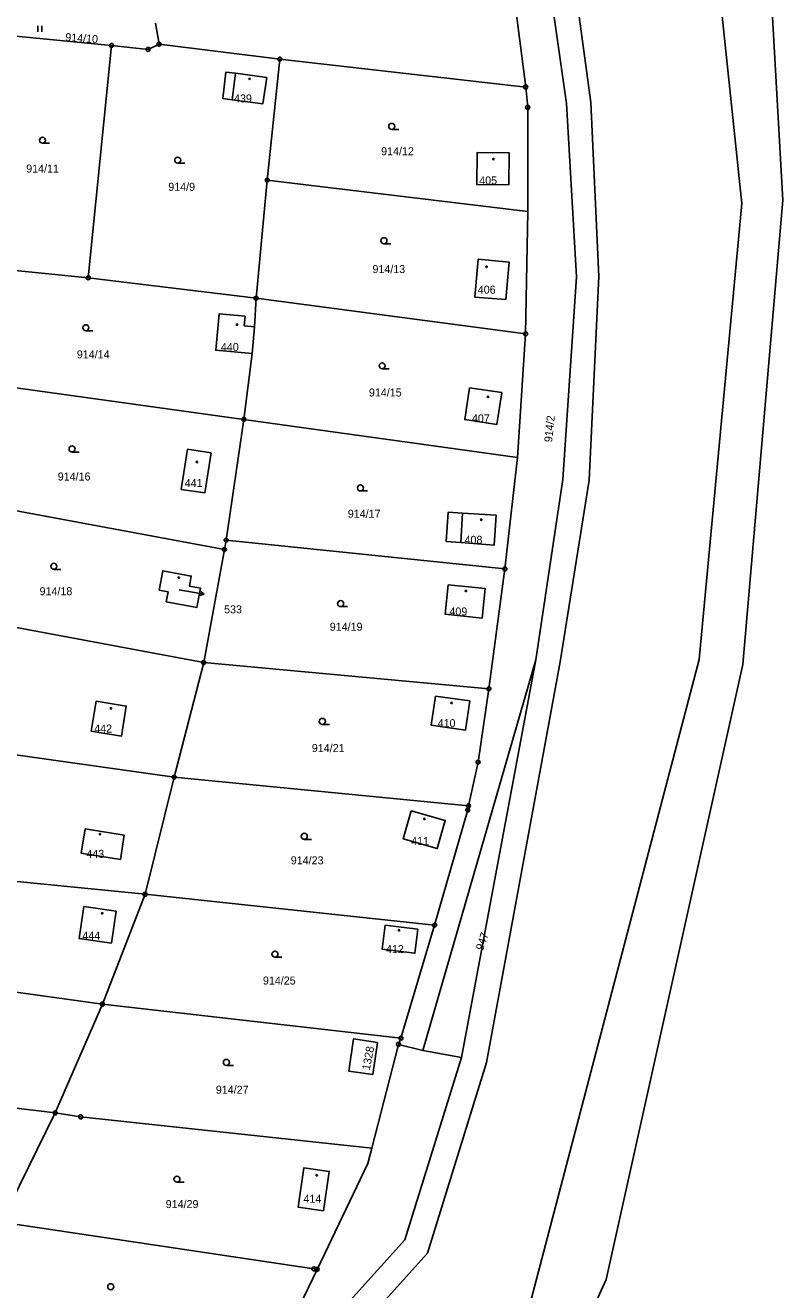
# Model space of a CAD drawing. Extents: x -745926 to -742978, y -968282 to -965689.
# Drawn here: x -744074.2 to -743979.6, y -968038.9 to -967880.9 of the extents above; entities that cross this region are included whole.
import ezdxf

# ---------------------------------------------------------------- set-up
doc = ezdxf.new("R2010")
doc.units = 0
for name, color, linetype in [('Hranice parcel', 7, 'Continuous'), ('Parcelní čísla', 7, 'Continuous'), ('Pop  PČ popisy', 7, 'Continuous'), ('Vnitřní kresba', 7, 'Continuous'), ('Značky bodu BP', 7, 'Continuous'), ('Značky budov', 7, 'Continuous'), ('Značky kultur', 7, 'Continuous')]:
    doc.layers.add(name, color=color, linetype=linetype)

msp = doc.modelspace()

# ---------------------------------------------------------------- linework, layer by layer
at = {"layer": 'Hranice parcel'}
for p, q in [((-744013.88, -967871.59), (-744011.71, -967888.67)), ((-744057.93, -967880.69), (-744057.5, -967883.31)), ((-744076.69, -967882.2), (-744063.43, -967883.47)), ((-744063.43, -967883.47), (-744066.34, -967912.5)), ((-744057.5, -967883.31), (-744042.42, -967885.18)), ((-744043.99, -967900.3), (-744042.42, -967885.18)), ((-744042.42, -967885.18), (-744011.71, -967888.67)), ((-744045.39, -967915.05), (-744043.99, -967900.3)), ((-744043.99, -967900.3), (-744011.44, -967904.22)), ((-744011.44, -967904.22), (-744011.72, -967919.51)), ((-744066.34, -967912.5), (-744045.39, -967915.05)), ((-744045.57, -967918.61), (-744045.39, -967915.05)), ((-744045.39, -967915.05), (-744011.72, -967919.51)), ((-744045.89, -967921.98), (-744045.57, -967918.61)), ((-744011.72, -967919.51), (-744012.73, -967934.97)), ((-744046.92, -967930.19), (-744045.89, -967921.98)), ((-744081.74, -967925.39), (-744046.92, -967930.19)), ((-744049.12, -967945.28), (-744046.92, -967930.19)), ((-744046.92, -967930.19), (-744012.73, -967934.97)), ((-744012.73, -967934.97), (-744014.31, -967948.88)), ((-744084.27, -967939.93), (-744049.34, -967946.46)), ((-744049.34, -967946.46), (-744049.12, -967945.28)), ((-744049.12, -967945.28), (-744014.31, -967948.88)), ((-744051.92, -967960.57), (-744049.34, -967946.46)), ((-744014.31, -967948.88), (-744016.31, -967963.85)), ((-744086.86, -967954.05), (-744051.92, -967960.57)), ((-744010.44, -967960.22), (-744024.55, -968009.03)), ((-744019.73, -968009.91), (-744010.44, -967960.22)), ((-744055.61, -967974.9), (-744051.92, -967960.57)), ((-744051.92, -967960.57), (-744016.31, -967963.85)), ((-744093.25, -967969.59), (-744055.61, -967974.9)), ((-744059.25, -967989.53), (-744055.61, -967974.9)), ((-744055.61, -967974.9), (-744018.86, -967978.48)), ((-744100.21, -967985.49), (-744059.25, -967989.53)), ((-744064.58, -968003.26), (-744059.25, -967989.53)), ((-744059.25, -967989.53), (-744023.1, -967993.38)), ((-744023.1, -967993.38), (-744027.29, -968007.5)), ((-744105.52, -967997.54), (-744064.58, -968003.26)), ((-744070.47, -968016.85), (-744064.58, -968003.26)), ((-744064.58, -968003.26), (-744027.29, -968007.5)), ((-744027.29, -968007.5), (-744027.6, -968008.29)), ((-744027.6, -968008.29), (-744030.93, -968021.24)), ((-744024.55, -968009.03), (-744027.6, -968008.29)), ((-744019.73, -968009.91), (-744024.55, -968009.03)), ((-744111.82, -968011.94), (-744070.47, -968016.85)), ((-744077.16, -968030.5), (-744070.47, -968016.85))]:
    msp.add_line(p, q, dxfattribs=at)
for points in [[(-744010.44, -967960.22), (-744007.08, -967937.69), (-744005.36, -967912.38), (-744006.62, -967890.72), (-744010, -967867.02), (-744009.12, -967862.36)], [(-744014.05, -968065.04), (-744001.65, -968037.67), (-743984.6, -967960.81), (-743979.62, -967902.8), (-743981.26, -967873.23)], [(-744057.5, -967883.31), (-744058.87, -967883.96), (-744063.43, -967883.47)], [(-744044.03, -967887.46), (-744047.94, -967886.95), (-744049.14, -967886.8), (-744049.54, -967890.09), (-744048.35, -967890.25), (-744044.52, -967890.76), (-744044.03, -967887.46)], [(-744011.71, -967888.67), (-744011.46, -967891.2), (-744011.44, -967904.22)], [(-744013.81, -967900.88), (-744013.79, -967896.88), (-744017.79, -967896.86), (-744017.81, -967900.86), (-744013.81, -967900.88)], [(-744079.82, -967911.15), (-744078.78, -967911.25), (-744066.34, -967912.5)], [(-744018.08, -967914.92), (-744014.18, -967915.21), (-744013.78, -967910.53), (-744017.66, -967910.19), (-744018.08, -967914.92)], [(-744045.57, -967918.61), (-744046.86, -967918.49), (-744046.75, -967917.3), (-744049.99, -967916.99), (-744050.42, -967921.56), (-744045.89, -967921.98)], [(-744018.73, -967926.23), (-744019.33, -967930.22), (-744015.31, -967930.83), (-744014.7, -967926.84), (-744018.73, -967926.23)], [(-744051.01, -967934.37), (-744053.93, -967933.92), (-744054.72, -967938.94), (-744051.8, -967939.39), (-744051.01, -967934.37)], [(-744019.59, -967941.89), (-744021.39, -967941.77), (-744021.64, -967945.47), (-744019.8, -967945.59), (-744015.64, -967945.9), (-744015.39, -967942.17), (-744019.59, -967941.89)], [(-744057.49, -967951.55), (-744056.37, -967951.76), (-744056.6, -967952.98), (-744052.79, -967953.7), (-744052.34, -967951.28), (-744053.71, -967951.02), (-744053.48, -967949.78), (-744057.03, -967949.11), (-744057.49, -967951.55)], [(-744021.38, -967950.85), (-744021.77, -967954.53), (-744017.16, -967955.03), (-744016.77, -967951.34), (-744021.38, -967950.85)], [(-744022.98, -967964.77), (-744023.5, -967968.42), (-744019.24, -967969.03), (-744018.7, -967965.38), (-744022.98, -967964.77)], [(-744016.31, -967963.85), (-744017.66, -967973.03), (-744018.86, -967978.48)], [(-744065.36, -967965.4), (-744065.97, -967969.17), (-744062.2, -967969.78), (-744061.59, -967966.01), (-744065.36, -967965.4)], [(-744026, -967979.12), (-744027.01, -967982.59), (-744022.79, -967983.82), (-744021.76, -967980.3), (-744026, -967979.12)], [(-744018.86, -967978.48), (-744018.95, -967978.99), (-744023.1, -967993.38)], [(-744066.74, -967981.37), (-744067.22, -967984.4), (-744062.32, -967985.18), (-744061.84, -967982.15), (-744066.74, -967981.37)], [(-744063.45, -967995.65), (-744062.87, -967991.65), (-744066.89, -967991.06), (-744067.48, -967995.06), (-744063.45, -967995.65)], [(-744025.18, -967993.91), (-744029.25, -967993.41), (-744029.62, -967996.39), (-744025.55, -967996.9), (-744025.18, -967993.91)], [(-744030.22, -968008.06), (-744030.81, -968012.07), (-744033.82, -968011.63), (-744033.22, -968007.61), (-744030.22, -968008.06)], [(-744238.47, -968250.81), (-744228.48, -968220.23), (-744215.49, -968202.15), (-744184.43, -968175.45), (-744137.25, -968142.28), (-744118.9, -968127.71), (-744107.2, -968119.2), (-744080.31, -968095.84), (-744060.74, -968076.33), (-744040.78, -968053.44), (-744033.64, -968040.28), (-744026.79, -968032.71), (-744019.73, -968009.91)], [(-744070.47, -968016.85), (-744067.29, -968017.34), (-744030.93, -968021.24)], [(-744030.93, -968021.24), (-744031.42, -968023.15), (-744037.77, -968036.4)], [(-744036.95, -968029.09), (-744036.25, -968024.15), (-744039.41, -968023.7), (-744040.11, -968028.64), (-744036.95, -968029.09)], [(-744077.16, -968030.5), (-744038.16, -968036.34), (-744037.77, -968036.4)], [(-744037.77, -968036.4), (-744040.52, -968042.14), (-744046.13, -968050.07)]]:
    msp.add_lwpolyline(points, dxfattribs=at)
at = {"layer": 'Pop  PČ popisy'}
for p, q in [((-744054.99, -967951.49), (-744053.33, -967951.78)), ((-744053.33, -967951.78), (-744051.85, -967952.04)), ((-744051.85, -967952.04), (-744052.39, -967952.2)), ((-744051.85, -967952.04), (-744052.3, -967951.71))]:
    msp.add_line(p, q, dxfattribs=at)
at = {"layer": 'Vnitřní kresba'}
for p, q in [((-744003.59, -967890.59), (-744006.8, -967866.88)), ((-743987.62, -967875.34), (-743984.73, -967903.21)), ((-744047.94, -967886.95), (-744048.35, -967890.25)), ((-744002.57, -967912.33), (-744003.59, -967890.59)), ((-743984.73, -967903.21), (-743990.05, -967960.19)), ((-744003.8, -967937.79), (-744002.57, -967912.33)), ((-744007.4, -967960.49), (-744003.8, -967937.79)), ((-744019.59, -967941.89), (-744019.8, -967945.59)), ((-743990.05, -967960.19), (-744017.1, -968063.19)), ((-744016.6, -968010.57), (-744007.4, -967960.49)), ((-744023.98, -968034.39), (-744016.6, -968010.57)), ((-744030.76, -968041.91), (-744023.98, -968034.39))]:
    msp.add_line(p, q, dxfattribs=at)
at = {"layer": 'Značky bodu BP'}
for centre, radius in [((-744063.43, -967883.47), 0.25), ((-744063.43, -967883.47), 0.0152), ((-744058.87, -967883.96), 0.25), ((-744058.87, -967883.96), 0.0152), ((-744057.5, -967883.31), 0.25), ((-744057.5, -967883.31), 0.0152), ((-744042.42, -967885.18), 0.25), ((-744042.42, -967885.18), 0.0152), ((-744011.71, -967888.67), 0.25), ((-744011.71, -967888.67), 0.0152), ((-744011.46, -967891.2), 0.25), ((-744011.46, -967891.2), 0.0152), ((-744043.99, -967900.3), 0.25), ((-744043.99, -967900.3), 0.0152), ((-744066.34, -967912.5), 0.25), ((-744066.34, -967912.5), 0.0152), ((-744045.39, -967915.05), 0.25), ((-744045.39, -967915.05), 0.0152), ((-744011.72, -967919.51), 0.25), ((-744011.72, -967919.51), 0.0152), ((-744046.92, -967930.19), 0.25), ((-744046.92, -967930.19), 0.0152), ((-744049.12, -967945.28), 0.25), ((-744049.12, -967945.28), 0.0152), ((-744049.34, -967946.46), 0.25), ((-744049.34, -967946.46), 0.0152), ((-744014.31, -967948.88), 0.25), ((-744014.31, -967948.88), 0.0152), ((-744051.92, -967960.57), 0.25), ((-744051.92, -967960.57), 0.0152), ((-744016.31, -967963.85), 0.25), ((-744016.31, -967963.85), 0.0152), ((-744017.66, -967973.03), 0.25), ((-744017.66, -967973.03), 0.0152), ((-744055.61, -967974.9), 0.25), ((-744055.61, -967974.9), 0.0152), ((-744018.95, -967978.99), 0.25), ((-744018.86, -967978.48), 0.25), ((-744018.95, -967978.99), 0.0152), ((-744018.86, -967978.48), 0.0152), ((-744059.25, -967989.53), 0.25), ((-744059.25, -967989.53), 0.0152), ((-744023.1, -967993.38), 0.25), ((-744023.1, -967993.38), 0.0152), ((-744064.58, -968003.26), 0.25), ((-744064.58, -968003.26), 0.0152), ((-744027.29, -968007.5), 0.25), ((-744027.29, -968007.5), 0.0152), ((-744027.6, -968008.29), 0.25), ((-744027.6, -968008.29), 0.0152), ((-744070.47, -968016.85), 0.25), ((-744070.47, -968016.85), 0.0152), ((-744067.29, -968017.34), 0.25), ((-744067.29, -968017.34), 0.0152), ((-744038.16, -968036.34), 0.25), ((-744037.77, -968036.4), 0.25), ((-744038.16, -968036.34), 0.0152), ((-744037.77, -968036.4), 0.0152)]:
    msp.add_circle(centre, radius, dxfattribs=at)
at = {"layer": 'Značky budov'}
for centre in [(-744046.19, -967887.64), (-744015.75, -967897.67), (-744016.6, -967911.13), (-744047.77, -967918.36), (-744016.42, -967927.39), (-744052.77, -967935.52), (-744017.27, -967942.73), (-744055.04, -967949.95), (-744019.18, -967951.63), (-744063.52, -967966.31), (-744020.97, -967965.61), (-744024.36, -967980.11), (-744064.88, -967982.02), (-744064.59, -967991.9), (-744027.52, -967994.02), (-744037.81, -968024.63)]:
    msp.add_circle(centre, 0.0875, dxfattribs=at)
at = {"layer": 'Značky kultur'}
for p, q in [((-744072.63, -967881.75), (-744072.63, -967881)), ((-744072.12, -967881.75), (-744072.12, -967881)), ((-744028.45, -967893.96), (-744027.57, -967893.96)), ((-744072.05, -967895.69), (-744071.17, -967895.69)), ((-744055.17, -967898.18), (-744054.29, -967898.18)), ((-744029.42, -967908.25), (-744028.54, -967908.25)), ((-744066.64, -967919.12), (-744065.76, -967919.12)), ((-744029.64, -967923.88), (-744028.76, -967923.88)), ((-744068.37, -967934.27), (-744067.49, -967934.27)), ((-744032.35, -967939.14), (-744031.47, -967939.14)), ((-744070.64, -967948.93), (-744069.76, -967948.93)), ((-744034.83, -967953.59), (-744033.95, -967953.59)), ((-744037.11, -967968.31), (-744036.23, -967968.31)), ((-744039.36, -967982.67), (-744038.48, -967982.67)), ((-744043.03, -967997.39), (-744042.15, -967997.39)), ((-744049.09, -968010.92), (-744048.21, -968010.92)), ((-744055.26, -968025.51), (-744054.38, -968025.51))]:
    msp.add_line(p, q, dxfattribs=at)
for centre in [(-744028.45, -967893.58), (-744072.05, -967895.31), (-744055.17, -967897.8), (-744029.42, -967907.87), (-744066.64, -967918.74), (-744029.64, -967923.5), (-744068.37, -967933.89), (-744032.35, -967938.76), (-744070.64, -967948.55), (-744034.83, -967953.21), (-744037.11, -967967.93), (-744039.36, -967982.29), (-744043.03, -967997.01), (-744049.09, -968010.54), (-744055.26, -968025.13), (-744063.54, -968038.56)]:
    msp.add_circle(centre, 0.375, dxfattribs=at)

# ---------------------------------------------------------------- texts
at = {"layer": 'Parcelní čísla'}
for s, rotation, p in [('914/10', 356, (-744069.24, -967882.91)), ('914/2', 84, (-744008.42, -967933.09)), ('947', 71, (-744017.04, -967996.62)), ('1328', 79, (-744031.19, -968011.56))]:
    msp.add_text(s, height=1, rotation=rotation, dxfattribs=at).set_placement(p)
for s, p in [('439', (-744048.14, -967890.59)), ('914/12', (-744029.77, -967897.19)), ('914/11', (-744074.09, -967899.35)), ('405', (-744017.52, -967900.84)), ('914/9', (-744056.35, -967901.63)), ('914/13', (-744030.85, -967911.91)), ('406', (-744017.7, -967914.48)), ('440', (-744049.78, -967921.65)), ('914/14', (-744067.77, -967922.57)), ('914/15', (-744031.29, -967927.33)), ('407', (-744018.43, -967930.57)), ('914/16', (-744070.15, -967937.83)), ('441', (-744054.3, -967938.64)), ('914/17', (-744033.93, -967942.48)), ('408', (-744019.35, -967945.74)), ('914/18', (-744072.42, -967952.16)), ('533', (-744049.38, -967954.43)), ('409', (-744021.24, -967954.69)), ('914/19', (-744036.18, -967956.6)), ('410', (-744022.71, -967968.65)), ('442', (-744065.59, -967969.32)), ('914/21', (-744038.42, -967971.76)), ('411', (-744026.01, -967983.38)), ('443', (-744066.58, -967984.98)), ('914/23', (-744041.05, -967985.79)), ('444', (-744067.08, -967995.2)), ('412', (-744029.16, -967996.88)), ('914/25', (-744044.53, -968000.81)), ('914/27', (-744050.41, -968014.45)), ('914/29', (-744056.67, -968028.74)), ('414', (-744039.46, -968028.07))]:
    msp.add_text(s, height=1, dxfattribs=at).set_placement(p)

doc.saveas('drawing.dxf')
